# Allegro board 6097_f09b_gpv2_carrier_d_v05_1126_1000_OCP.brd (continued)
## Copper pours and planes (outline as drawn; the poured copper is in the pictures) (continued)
GND on IN1 (solid shape): 113.69,146.17 113.75,146.1 113.75,145.72 113.54,145.51 112.47,145.51 111,146.98 18.5,146.98 17.8,146.7 17.52,146 17.52,125.5 16.63,123.37 14.5,122.48 2,122.48 1.3,122.2 1.02,121.5 1.02,2 1.3,1.3 2,1.02 94.1,1.02 94.3,0.82 207.52,0.82 207.71,1.02 208,1.02 208.7,1.3 208.98,2 208.98,2.29 209,2.3 209,22.81 208.98,22.83 208.98,121.5 208.7,122.2 208,122.48 195.5,122.48 193.37,123.37 192.48,125.5 192.48,146 192.2,146.7 191.5,146.98 170.43,146.98 170.43,147.49 191.5,147.49 192.55,147.05 192.99,146 192.99,125.5 193.73,123.73 195.5,122.99 208,122.99 209.06,122.55 209.49,121.5 209.49,2 209.06,0.94 208,0.51 2,0.51 0.94,0.94 0.51,2 0.51,121.5 0.94,122.55 2,122.99 14.5,122.99 16.27,123.73 17.01,125.5 17.01,146 17.45,147.05 18.5,147.49 113.69,147.49
GND on IN1 (solid shape): outline of 6714 points within 161.24,2.17 207.32,50.16
GND on GND1 (solid shape): outline of 20227 points within 0.51,0.51 209.49,147.49
GND on VCC (solid shape): 114.63,40.62 116.4,40.62 116.56,40.45 116.56,37.53 114.78,35.75 106.34,35.75 106.01,36.08 106.01,39.36 107.98,41.32 113.92,41.32
GND on VCC (solid shape): 202.68,48.12 202.68,47.12 205.4,44.4 205.4,39.23 205.54,39.09 205.54,33.25 203.6,31.31 203.6,26.16 203.33,25.89 203.33,25.89 203.15,25.7 186.42,25.7 186.11,26.02 186.11,26.14 186.08,26.14 186.08,27.41 186.1,27.43 186.13,27.48 186.15,27.53 186.17,27.58 186.18,27.64 186.18,27.69 186.17,27.75 186.15,27.8 186.13,27.85 186.1,27.9 186.08,27.92 186.08,32.5 200.9,32.5 200.9,31.84 201.15,31.59 202.9,31.59 203.06,31.75 203.06,34.59 202.92,34.74 202.14,34.74 201.98,34.57 201.98,32.75 201.79,32.57 200.97,32.57 200.9,32.5 186.08,32.5 186.08,32.68 186.15,32.71 186.19,32.74 186.23,32.78 186.26,32.82 186.29,32.86 186.32,32.91 186.33,32.96 186.34,33.02 186.34,33.07 186.33,33.12 186.32,33.17 186.29,33.22 186.26,33.27 186.23,33.31 186.19,33.34 186.15,33.37 186.08,33.41 186.08,42.86 184.49,44.45 184.49,44.46 183.9,45.04 183.9,48 184.11,48.2 202.59,48.2
GND on VCC (solid shape): 206.02,105.7 206.29,105.7 206.62,105.38 206.65,105.21 206.51,105.12 206.34,105.12 206.12,104.89 206.12,104.57 206.34,104.34 206.66,104.34 206.85,104.53 206.93,104.54 206.98,104.47 206.98,104.33 207.19,104.12 207.19,104.08 207.41,103.86 207.45,103.86 208.29,103.01 208.29,77.56 207.53,76.8 207.53,73.58 208.25,72.86 208.25,58.25 206.4,56.41 206.4,50.29 208.32,48.37 208.32,39.03 207.63,38.35 207.63,30.71 207.49,30.57 207.08,30.57 206.9,30.74 206.9,31.42 207.36,31.87 207.36,38.54 208.02,39.2 208.02,48.24 206.06,50.2 206.06,56.68 207.93,58.55 207.93,59.43 208.01,59.67 207.93,59.91 207.93,72.65 207.19,73.38 207.19,77.02 207.99,77.81 207.99,101.82 205.55,104.26 205.55,105.77 205.96,105.77
GND on VCC1 (solid shape): 114.63,40.62 116.4,40.62 116.56,40.45 116.56,37.53 114.78,35.75 106.34,35.75 106.01,36.08 106.01,39.36 107.98,41.32 113.92,41.32
GND on VCC1 (solid shape): outline of 1285 points within 186.08,13.61 208.98,106.52
GND on GND2 (solid shape): outline of 23656 points within 0.51,0.51 209.49,147.49
GND on IN2 (solid shape): 121.76,37.61 121.87,37.51 121.87,36.61 121.69,36.43 118.25,36.43 118.04,36.64 118.04,40.33 118.14,40.43 121.76,40.43
GND on IN2 (solid shape): 33.5,39.43 33.42,39.35 33.42,39.19 33.01,38.79 33.01,36.92 31.9,36.92 31.53,36.55 30.24,36.55 30.03,36.76 30.03,39.68 30.43,40.08 32.86,40.08
GND on IN2 (solid shape): 197.16,32.56 197.27,32.52 197.41,32.37 197.41,30.61 197.32,30.47 197.15,30.5 196.58,31.07 196.58,32.24 196.63,32.36 196.75,32.4 196.91,32.42 197.05,32.51
GND on IN2 (solid shape): 111.19,39.36 111.19,36.26 110.43,35.5 106.48,35.5 106.28,35.7 106.28,36.75 108.28,36.75 108.28,36.7 108.3,36.64 108.32,36.59 108.34,36.54 108.38,36.5 108.42,36.46 108.46,36.43 108.51,36.4 108.56,36.38 108.62,36.37 108.68,36.37 108.73,36.38 108.78,36.39 108.84,36.41 108.88,36.44 108.93,36.48 108.96,36.52 108.99,36.57 109.02,36.62 109.03,36.67 109.04,36.73 109.04,36.78 109.03,36.84 109.02,36.89 108.99,36.94 108.96,36.99 108.93,37.03 108.88,37.06 108.84,37.09 108.78,37.12 108.73,37.13 108.68,37.14 108.62,37.13 108.56,37.12 108.51,37.11 108.46,37.08 108.42,37.05 108.38,37.01 108.34,36.96 108.32,36.92 108.3,36.86 108.28,36.81 108.28,36.75 106.28,36.75 106.28,39.58 106.7,40.01 110.53,40.01
GND on IN2 (solid shape): outline of 287 points within 15.58,19.54 22.54,27.85
GND on IN2 (solid shape): 113.69,146.03 114.23,145.49 115.07,145.49 115.56,145.99 115.56,147.49 118.44,147.49 118.44,146.16 118.44,146.03 118.98,145.48 119.79,145.48 120.31,146 120.31,147.49 120.31,147.49 167.26,147.49 167.26,146.98 128.23,146.98 128.23,146.98 127.25,146.98 125.55,145.28 111.89,145.28 111.32,145.86 111.32,146.74 111.08,146.98 18.5,146.98 17.8,146.7 17.52,146 17.52,125.5 16.63,123.37 14.5,122.48 2,122.48 1.3,122.2 1.02,121.5 1.02,2 1.3,1.3 2,1.02 208,1.02 208.7,1.3 208.98,2 208.98,121.5 208.7,122.2 208,122.48 195.5,122.48 193.37,123.37 192.48,125.5 192.48,146 192.2,146.7 191.5,146.98 170.62,146.98 170.62,147.49 191.5,147.49 192.55,147.05 192.99,146 192.99,125.5 193.73,123.73 195.5,122.99 208,122.99 209.06,122.55 209.49,121.5 209.49,2 209.06,0.94 208,0.51 2,0.51 0.94,0.94 0.51,2 0.51,121.5 0.94,122.55 2,122.99 14.5,122.99 16.27,123.73 17.01,125.5 17.01,146 17.45,147.05 18.5,147.49 113.69,147.49
GND on IN2 (solid shape): outline of 4770 points within 160.38,2.18 204.34,50.9
GND on GND3 (solid shape): outline of 24065 points within 0.51,0.51 209.49,147.49
P0V9_BOOTC on TOP (solid shape): 207.86,41.1 207.86,39.37 207.81,39.32 207.22,39.32 207.13,39.41 207.13,41.22 207.19,41.29 207.66,41.29
P0V9_VCC on TOP (solid shape): 208.73,38.35 208.73,37.55 207.79,37.55 207.71,37.47 207.55,37.47 207.54,37.46 207.46,37.45 207.41,37.52 207.41,37.75 208.05,38.39 208.69,38.39
P0V9_VDRV1 on TOP (solid shape): 201.23,37.15 201.23,36.41 201.2,36.38 200.28,36.38 200.18,36.47 198.93,36.47 198.76,36.3 198.76,34.75 198.15,34.75 198.15,35.43 198.09,35.48 197.31,35.48 197.28,35.51 197.28,37.06 197.49,37.27 201.11,37.27
P0V92 on TOP (solid shape): 204.41,50.11 204.41,44.82 203.59,43.99 201.01,43.99 201,43.98 200.92,43.98 200.54,43.61 200.54,42.25 200.42,42.13 200.35,42.2 200.34,42.22 199.94,42.53 199.59,42.16 199.59,42.09 188.31,42.09 188.14,42.25 188.14,44.11 187.7,44.55 184.88,44.55 184.75,44.68 184.75,48.69 184.95,48.88 187.32,48.88 187.46,48.74 187.46,47.26 187.48,47.24 187.48,47.23 187.81,46.9 196.35,46.9 196.43,46.98 196.7,46.98 196.8,47.09 196.8,49.83 197.33,50.36 204.16,50.36
P0V92 on BOTTOM (solid shape): 203.59,46.67 203.59,42.48 203.3,42.19 200.35,42.19 200.34,42.25 199.97,42.53 199.6,42.25 199.58,42.19 186.84,42.19 186.83,42.19 180.6,42.19 180.56,42.23 180.56,44.43 181.82,45.69 184.48,45.69 184.7,45.91 184.7,48.7 184.91,48.91 187.32,48.91 187.46,48.77 187.46,47.34 187.88,46.92 195.4,46.92 195.89,47.41 195.89,49.46 196.21,49.78 200.48,49.78
P0V92 on BOTTOM (solid shape): outline of 407 points within 190.91,93.13 204.56,101.19
P0V92 on BOTTOM (solid shape): outline of 3945 points within 176.33,70.62 191.16,88.48
P0V92 on IN1 (solid shape): outline of 3053 points within 176.33,72.8 190.83,88.24
P0V92 on VCC1 (solid shape): outline of 1190 points within 140.16,40.45 208.98,122.48
P0V92_SENSE+ on VCC (solid shape): outline of 230 points within 205.55,30.57 208.98,106.62
P1V8 on TOP (solid shape): 21.42,26.36 21.42,24.11 21.31,24.01 18.07,24.01 17.91,24.16 17.91,26.34 18.04,26.47 21.3,26.47
P1V8 on TOP (solid shape): 207.24,101.93 207.24,101.73 207.29,101.68 208.31,101.68 208.73,101.25 208.73,76.9 208.69,76.79 208.58,76.75 208.54,76.74 208.5,76.73 208.23,76.73 208.03,76.94 208.03,88.59 208.04,88.69 208.03,88.78 208.03,89.67 208.04,89.77 208.03,89.86 208.03,90.23 207.68,90.57 206.13,90.57 205.89,90.82 205.84,90.82 205.84,102.06 205.89,102.11 207.06,102.11
P1V8 on BOTTOM (solid shape): 2.44,40.23 2.44,38.53 2.13,38.23 1.3,38.23 1.27,38.25 1.27,40.28 2.39,40.28
P1V8 on BOTTOM (solid shape): 21.42,26.36 21.42,24.62 21.28,24.48 18.09,24.48 17.91,24.66 17.91,26.34 18.04,26.47 21.3,26.47
P1V8 on BOTTOM (solid shape): 205.06,81.36 205.06,78.11 204.83,77.88 203.41,77.88 203.41,78.81 203.76,79.17 203.76,79.25 203.86,79.35 203.86,81.25 204.02,81.41 205.01,81.41
P1V8 on BOTTOM (solid shape): 193.48,5.12 193.48,4.33 193.67,4.13 193.67,2.2 193.51,2.04 191.79,2.04 191.58,2.25 191.58,3.88 191.28,4.18 188.79,4.18 188.76,4.21 188.76,4.72 188.76,4.72 190.63,4.72 191.09,5.19 193.41,5.19
P1V8 on BOTTOM (solid shape): 3.22,32.43 3.31,32.3 3.43,32.22 3.45,32.21 3.82,31.84 3.82,30.97 3.7,30.85 2.46,30.85 2.37,30.94 2.37,32.43 2.39,32.45 3.21,32.45
P1V8 on BOTTOM (solid shape): 195.79,73.03 195.79,72.25 195.62,72.25 195.57,72.25 195.51,72.24 194.89,72.24 194.76,72.35 194.59,72.39 194.56,72.39 194.53,72.42 194.5,72.59 194.63,72.68 194.87,72.79 194.98,73.04 195.03,73.14 195.13,73.18 195.64,73.18
P1V8 on BOTTOM (solid shape): 192.81,75.21 192.81,74.84 192.79,74.81 192.57,74.49 192.68,74.12 192.68,73.85 192.83,73.69 193.28,73.69 193.33,73.65 193.53,73.58 193.73,73.6 193.78,73.61 194.24,73.15 194.24,73.11 194.24,73 194.27,72.89 194.3,72.84 194.21,72.75 194.03,72.92 194.03,72.98 193.97,72.98 193.8,73.15 191.45,73.15 191.2,73.4 191.27,73.47 191.34,73.58 191.37,73.72 191.37,74.29 191.78,74.7 191.79,74.7 191.9,74.82 191.96,74.97 191.96,74.99 192.25,75.29 192.73,75.29
P1V8 on BOTTOM (solid shape): outline of 908 points within 189.74,82.81 199.51,90.69
P1V8 on VCC (solid shape): outline of 14675 points within 1.02,1.02 208.98,146.98
P1V8 on IN2 (solid shape): outline of 2105 points within 188.73,69.79 199.18,86.29
P1V8 on IN2 (solid shape): outline of 3968 points within 61.89,2.2 149.25,46.23
P3V3 on TOP (solid shape): 192.04,140.81 192.04,139.77 191.45,139.18 187.59,139.18 187.54,139.23 187.54,140.38 188.55,140.38 188.59,140.38 188.63,140.39 189.87,140.39 190.4,140.91 191.93,140.91
P3V3 on BOTTOM (solid shape): 8.26,108.14 8.26,106.23 7.98,105.95 1.38,105.95 1.31,106.02 1.31,106.86 1.42,106.97 3.58,106.97 3.96,107.34 3.96,107.7 3.97,107.72 4.03,107.94 3.97,108.17 3.96,108.19 3.96,108.27 4.02,108.33 8.07,108.33
P3V3 on VCC (solid shape): outline of 630 points within 82.38,143.29 142.38,146.98
P3V3_BOOTC_2 on TOP (solid shape): 172.57,23.42 172.57,21.96 172.52,21.92 171.95,21.92 171.92,21.95 171.92,23.4 171.97,23.45 172.54,23.45
P3V3_BOOTC_3 on TOP (solid shape): 195.21,38.29 195.21,36.76 195.14,36.69 194.55,36.69 194.49,36.75 194.49,37.15 194.5,37.15 194.5,37.38 194.32,37.55 194.32,38.38 194.36,38.41 195.09,38.41
P3V3_DB1200 on BOTTOM (solid shape): outline of 578 points within 55.35,55.1 71.53,73.2
P3V3_DB1200_VDDA on BOTTOM (solid shape): 68.28,67.06 69.21,67.06 69.49,66.78 69.49,65.85 69.04,65.41 68.63,65.41 68.63,65.41 66.6,65.41 66.47,65.53 66.47,66.09 66.55,66.22 66.7,66.22 67.27,66.56 66.7,66.89 66.55,66.89 66.47,67.02 66.47,67.58 66.63,67.73 67.6,67.73
P3V3_DB1200_VDDR on BOTTOM (solid shape): 66.1,67.25 66.1,65.99 65.58,65.48 63.8,65.48 63.55,65.74 63.55,66.59 64.5,66.59 64.51,66.54 64.52,66.48 64.54,66.43 64.57,66.38 64.6,66.34 64.64,66.3 64.69,66.27 64.74,66.24 64.79,66.22 64.84,66.21 64.9,66.21 64.96,66.22 65.01,66.23 65.06,66.25 65.11,66.28 65.15,66.32 65.19,66.36 65.22,66.41 65.24,66.46 65.26,66.51 65.27,66.57 65.27,66.62 65.26,66.68 65.24,66.73 65.22,66.78 65.19,66.83 65.15,66.87 65.11,66.9 65.06,66.93 65.01,66.95 64.96,66.97 64.9,66.97 64.84,66.97 64.79,66.96 64.74,66.94 64.69,66.92 64.64,66.89 64.6,66.85 64.57,66.8 64.54,66.76 64.52,66.7 64.51,66.65 64.5,66.59 63.55,66.59 63.55,67.31 63.68,67.43 65.92,67.43
P3V3_M2A on TOP (solid shape): outline of 125 points within 23.36,111.32 31.14,114.83
P3V3_M2A_L on TOP (solid shape): outline of 406 points within 19.38,117.63 37.84,126.82
P3V3_M2B on TOP (solid shape): 55.2,114.65 55.2,113.75 55.14,113.63 55,113.61 54.5,113.24 55,112.88 55.14,112.86 55.2,112.74 55.2,112.19 55.2,112.18 55.2,112.14 54.99,111.94 54.24,111.94 53.38,111.07 49.24,111.07 49.23,111.06 48.93,111.06 48.63,111.36 48.63,111.89 48.63,111.96 48.04,112.56 48.04,114.35 48.07,114.38 50.23,114.38 50.34,114.33 50.38,114.21 50.38,114.17 50.38,113.54 50.77,113.14 51.16,113.54 51.16,114.17 51.16,114.25 51.13,114.32 51.11,114.37 51.32,114.58 51.32,114.77 51.39,114.83 55.01,114.83
P3V3_M2B_L on TOP (solid shape): outline of 97 points within 43.38,118.01 61.84,127.46
P3V3_M2C on TOP (solid shape): 80.16,113.61 80.16,112.44 80.06,112.34 79.95,112.29 79.84,112.34 79.31,112.33 79.31,111.8 79.35,111.69 79.3,111.58 79.12,111.4 79.08,111.4 77.94,110.26 73.7,110.26 73.53,110.44 73.53,111.17 72.56,112.14 72.56,113.07 72.82,113.32 75.14,113.32 75.26,113.27 75.29,113.15 75.29,113.1 75.29,112.52 75.61,112.2 76.17,112.2 76.17,112.76 76.08,112.85 76.08,113.1 76.07,113.16 76.05,113.24 76.05,113.32 76.15,113.32 76.26,113.43 78.55,113.43 78.93,113.81 79.96,113.81
P3V3_M2C_L on TOP (solid shape): outline of 100 points within 67.11,116.54 85.84,126.82
P3V3_M2D on TOP (solid shape): 105.91,113.84 105.91,113.43 105.85,113.31 105.71,113.29 105.21,112.93 105.71,112.57 105.85,112.55 105.91,112.42 105.91,111.26 105.63,110.98 102.7,110.98 102.57,110.85 98.67,110.85 98.4,111.12 98.4,114.04 98.45,114.1 100.54,114.1 100.65,114.05 100.69,113.93 100.69,113.9 100.69,113.29 101.08,112.89 101.48,113.29 101.48,113.9 101.47,113.95 101.46,114.01 101.46,114.1 101.56,114.1 101.67,114.21 105.54,114.21
P3V3_M2D_L on TOP (solid shape): outline of 96 points within 91.38,117.27 109.84,126.82
P3V3_M2E on TOP (solid shape): 128.78,114.14 128.78,112.5 128.57,112.29 127.42,112.29 126.27,111.14 123.02,111.14 122.89,111.27 122.89,111.93 122.38,112.44 122.38,114.25 124.49,114.25 124.6,114.2 124.64,114.08 124.64,114.03 124.64,113.4 124.95,113.08 125.51,113.08 125.51,113.64 125.43,113.73 125.43,114.03 125.42,114.09 125.4,114.17 125.4,114.25 125.51,114.25 125.58,114.32 128.6,114.32
P3V3_M2E_L on TOP (solid shape): outline of 88 points within 115.38,117.45 133.84,126.82
P3V3_M2F on TOP (solid shape): 157.2,114.03 157.2,112.48 157.12,112.4 154.24,112.4 153.01,111.16 149.94,111.16 149.49,111.61 149.46,111.61 149.13,111.94 148.93,111.94 148.84,111.96 148.77,111.97 148.53,111.97 148.37,112.13 148.37,113.45 148.58,113.66 152.07,113.66 152.19,113.61 152.22,113.49 152.22,113.39 152.25,113.3 152.28,113.22 152.34,113.16 152.35,113.15 152.35,113.08 152.41,113.08 152.54,112.95 153.24,112.95 153.66,113.37 153.66,114.66 156.57,114.66
P3V3_M2F_L on TOP (solid shape): outline of 248 points within 139.38,117.6 157.84,126.82
P3V3_M2G on BOTTOM (solid shape): 159.79,116.27 160.25,115.81 161.04,115.81 161.2,115.97 161.27,115.97 161.27,116.04 161.37,116.19 161.39,116.37 161.43,116.48 161.54,116.53 163.48,116.53 163.58,116.4 163.6,116.37 163.6,116.34 163.6,115.51 163.62,115.49 163.62,114.28 163.25,113.91 163.23,113.91 163.11,113.86 163,113.78 162.8,113.58 162.1,113.58 161.85,113.32 158.98,113.32 158.73,113.58 158.67,113.58 158.62,113.62 157.74,113.62 157.64,113.61 157.56,113.58 157.54,113.58 157.39,113.58 157.38,113.63 157.27,113.8 157.11,113.91 157.06,113.93 157.06,116.01 157.8,116.75 159.79,116.75
P3V3_M2G_L on BOTTOM (solid shape): outline of 1181 points within 148.58,119.56 168.06,134.07
P3V3_M2H on BOTTOM (solid shape): 132.23,113.47 132.26,113.32 132.34,113.19 132.6,112.94 133.28,112.94 133.46,113.12 133.53,113.12 133.53,113.18 133.58,113.24 133.61,113.3 133.65,113.41 133.65,113.52 133.69,113.64 133.8,113.69 135.92,113.69 135.92,111.67 135.54,111.29 135.5,111.3 135.3,111.28 135.12,111.17 135.04,111.09 133.1,111.09 133.08,111.1 131.92,111.1 130.57,112.46 128.95,112.46 128.89,112.52 128.89,113.57 129.07,113.74 132.23,113.74
P3V3_M2H_L on BOTTOM (solid shape): outline of 1501 points within 124.58,116.84 144.43,134.14
P3V3_M2I on BOTTOM (solid shape): outline of 89 points within 104.78,110.27 112.08,113.25
P3V3_M2I_L on BOTTOM (solid shape): outline of 1368 points within 100.02,116.37 120.66,134.27
P3V3_M2J on BOTTOM (solid shape): 82.72,112.94 82.75,112.79 82.84,112.66 83.14,112.36 83.75,112.36 83.97,112.59 84.04,112.59 84.04,112.65 84.05,112.66 84.15,112.82 84.16,113 84.2,113.11 84.32,113.16 86.43,113.16 86.44,113.15 86.44,110.99 85.85,110.41 79.59,110.41 79.42,110.58 79.42,112.22 79.47,112.32 79.57,112.37 79.9,112.58 79.87,112.97 79.86,113.12 80,113.21 82.72,113.21
P3V3_M2J_L on BOTTOM (solid shape): outline of 1598 points within 75.71,116.34 96.09,134.07
P3V3_M2K on BOTTOM (solid shape): 58.82,113.84 58.82,113.21 58.9,113.13 59.23,113.13 59.23,113.04 59.19,112.91 58.63,112.91 58.23,112.52 58.63,112.13 59.39,112.13 59.54,112.16 59.67,112.24 59.98,112.55 59.98,112.88 59.98,112.92 59.97,112.95 60,113.08 60.12,113.13 61.73,113.13 61.73,113.09 62.26,113.09 62.26,113.09 62.26,111.92 61.29,110.94 61.29,110.37 60.81,109.9 59.85,109.9 59.83,109.94 59.47,110.22 59.05,110.08 58.86,109.9 57.36,109.9 57.09,110.02 56.76,109.93 56.71,109.95 56.4,110.09 56.09,109.96 56.03,109.9 55.04,109.9 55.02,109.95 54.71,110.26 54.29,110.15 54.24,110.1 54.08,110.25 54.08,113.48 54.23,113.63 54.33,113.67 54.43,113.64 54.81,113.58 55.05,113.87 55.06,113.93 58.73,113.93
P3V3_M2K_L on BOTTOM (solid shape): outline of 1979 points within 51.9,116.94 72.54,134.16
P3V3_M2L on BOTTOM (solid shape): 35.9,115.25 36.28,114.87 36.99,114.87 37.12,114.88 37.24,114.94 37.29,114.98 37.41,115.15 37.44,115.35 37.47,115.47 37.59,115.52 39.53,115.52 39.53,115.46 39.61,115.29 39.64,115.26 39.64,114.63 38.61,113.6 38.61,112.85 36.87,112.85 36.75,112.97 32.76,112.97 31.74,113.99 31.52,114.11 31.28,114.09 31.26,114.09 31.18,114.09 31.18,114.28 31.27,114.37 31.27,114.38 31.27,114.91 31.39,115.04 32.39,115.04 32.39,115.04 35.2,115.04 35.72,115.56 35.9,115.56
P3V3_M2L_L on BOTTOM (solid shape): outline of 1753 points within 25.83,118.19 50.87,134.16
P3V3_STBY on TOP (solid shape): 11.59,33.9 11.59,33.03 11.38,32.82 9.99,32.82 9.96,32.84 9.96,33.98 10.12,34.13 11.36,34.13
P3V3_STBY on TOP (solid shape): 16.89,18.99 16.89,16.75 16.79,16.64 15.81,16.64 15.69,16.76 15.69,19 15.75,19.05 16.83,19.05
P3V3_STBY on TOP (solid shape): 32.72,35.26 32.72,34.62 31.29,33.2 30.2,33.2 30.05,33.35 30.05,34.64 30.2,34.79 30.2,34.98 30.58,35.36 32.61,35.36
P3V3_STBY on TOP (solid shape): 112.14,31.85 114.07,31.85 114.07,30.79 112.19,30.79 111.71,31.04 111.2,31.21 111.18,31.22 110.36,32.03 110.36,32.44 110.54,32.61 111.38,32.61
P3V3_STBY on TOP (solid shape): 98.72,116.98 98.72,116.35 98.79,116.28 101.43,116.28 101.5,116.21 101.5,114.39 101.46,114.35 98.35,114.35 97.89,113.9 97.89,110.14 96.95,109.19 95.22,109.19 94.9,109.52 94.9,115.39 95.02,115.52 96.63,115.52 97.08,115.97 97.08,116.23 97.13,116.28 97.83,116.28 97.9,116.35 97.9,116.73 98.15,116.98 98.72,116.98
P3V3_STBY on TOP (solid shape): 187.73,44.09 187.73,40.31 185.9,38.48 185.9,33.86 185.34,33.3 185.34,26.57 185.04,26.26 161.93,26.26 161.75,26.44 161.75,29.82 161.04,30.53 161.04,33.76 161.38,34.1 178.73,34.1 179.82,33.01 182.47,33.01 182.79,33.33 182.79,39.88 182.53,40.14 181.4,40.14 181.2,40.34 181.2,40.98 181.19,40.98 181.19,43.95 181.51,44.27 187.55,44.27
P3V3_STBY on TOP (solid shape): 115.89,142.98 116.06,142.82 117.55,142.82 117.82,142.54 117.82,142.53 118.07,142.29 120.42,142.29 122.59,144.46 124.84,144.46 124.89,144.4 124.89,143.94 125.09,143.74 125.28,143.74 125.29,143.73 126.8,143.73 126.83,143.7 126.83,142.17 124.7,140.05 115.03,140.05 114.72,140.36 114.72,142.36 115.52,143.17 115.52,144.51 115.89,144.51
P3V3_STBY on TOP (solid shape): 73.32,116.19 73.32,115.62 73.46,115.48 76.07,115.48 76.12,115.44 76.12,113.65 76.04,113.58 72.65,113.58 72.28,113.95 71.94,113.95 71.72,113.73 71.72,113.36 71.93,113.16 72.28,113.16 72.31,113.13 72.31,109.76 72.51,109.55 73.29,109.55 73.33,109.52 73.33,109.08 73.26,109.01 72.66,109.01 72.33,108.69 72.33,108.37 72.19,108.23 70.19,108.23 70.02,108.4 70.02,111.79 69.39,112.42 69.39,115.39 69.49,115.48 72.59,115.48 72.64,115.54 72.64,116.08 72.76,116.2 73.31,116.2
P3V3_STBY on TOP (solid shape): 122.67,117.12 122.67,116.49 122.74,116.41 125.42,116.41 125.5,116.34 125.5,114.6 125.41,114.51 122,114.51 121.94,114.44 121.94,112.37 122.47,111.83 122.47,110.99 121.92,110.44 120.52,110.44 120.12,110.04 119.94,110.04 119.13,109.23 118.83,109.23 118.68,109.38 118.68,116.28 118.81,116.41 119.96,116.41 120.06,116.31 120.06,115.94 120.17,115.82 120.96,115.82 120.98,115.85 120.98,116.36 121.03,116.41 121.88,116.41 121.97,116.5 121.97,117.04 122.05,117.12 122.67,117.12
P3V3_STBY on TOP (solid shape): 48.41,117.25 48.41,116.63 48.5,116.54 49.55,116.54 49.94,116.54 51.07,116.54 51.07,114.69 51.01,114.63 47.85,114.63 47.66,114.83 47.12,114.83 46.86,114.57 46.86,114.35 47.19,114.02 47.49,114.02 47.56,113.94 47.56,112.6 48.38,111.78 48.38,111.25 48.71,110.92 48.71,110.15 48.57,110.01 44.96,110.01 44.78,110.19 44.78,116.38 44.78,116.48 44.87,116.58 45.39,116.58 45.65,116.84 46.21,116.84 46.5,116.54 47.64,116.54 47.74,116.64 47.74,117.12 47.88,117.27 48.39,117.27
P3V3_STBY on TOP (solid shape): 21.26,117.35 21.26,117.15 21.49,116.92 22.99,116.92 23.06,116.98 23.06,117.61 23.1,117.65 23.69,117.65 23.7,117.64 23.7,117.01 23.72,116.99 26.28,116.99 26.29,116.98 26.29,115.18 26.23,115.11 23.32,115.11 22.87,114.66 22.87,113.02 23.66,112.22 23.66,111.48 23.66,111.33 23.66,111.01 22.97,110.31 21.54,110.31 21.52,110.36 21.16,110.62 20.8,110.37 20.37,110.37 20.15,110.59 20.15,110.95 20.08,111.03 19.73,111.03 19.68,111.07 19.68,115.29 20.29,115.89 20.29,117.65 20.35,117.72 20.89,117.72
P3V3_STBY on TOP (solid shape): 146.37,116.74 146.37,116.13 146.69,115.81 149.64,115.81 149.71,115.88 149.71,116.42 149.8,116.52 150.25,116.52 150.25,115.83 150.28,115.81 152.86,115.81 152.86,113.97 152.8,113.91 148.45,113.91 148.03,113.49 148.03,112.44 147.91,112.33 147.73,112.33 147.19,112.26 147.26,111.72 147.29,111.67 147.28,111.62 147.2,111.42 147.21,111.2 147.18,111.07 147.06,111.01 144.62,111.01 144.3,111.33 144.3,116.77 144.46,116.93 146.18,116.93
P3V3_STBY on TOP (solid shape): 187.61,132.55 190.6,132.55 191.51,131.64 191.51,129.27 191.1,128.87 185.96,128.87 185.78,129.05 185.78,130.58 185.86,130.67 186.08,130.67 186.46,131.05 186.46,131.17 188.85,131.17 188.85,130.49 188.85,130.45 188.86,130.38 188.88,130.3 188.9,130.23 188.93,130.16 188.97,130.1 189.01,130.04 189.07,129.99 189.12,129.94 189.18,129.9 189.25,129.86 189.32,129.84 189.39,129.82 189.46,129.8 189.54,129.8 189.61,129.8 189.69,129.82 189.76,129.84 189.83,129.86 189.89,129.9 189.95,129.94 190.01,129.99 190.06,130.04 190.11,130.1 190.14,130.16 190.18,130.23 190.2,130.3 190.22,130.38 190.22,130.45 190.22,130.49 190.22,131.17 190.22,131.21 190.22,131.28 190.2,131.36 190.18,131.43 190.14,131.49 190.11,131.56 190.06,131.62 190.01,131.67 189.95,131.72 189.89,131.76 189.83,131.8 189.76,131.82 189.69,131.84 189.61,131.85 189.54,131.86 189.46,131.85 189.39,131.84 189.32,131.82 189.25,131.8 189.18,131.76 189.12,131.72 189.07,131.67 189.01,131.62 188.97,131.56 188.93,131.49 188.9,131.43 188.88,131.36 188.86,131.28 188.85,131.21 188.85,131.17 186.46,131.17 186.46,132.84 186.5,132.88 187.28,132.88
P3V3_STBY on BOTTOM (solid shape): 9.56,32.94 9.56,32.94 10.1,32.39 10.1,31.03 9.91,30.84 9.03,30.84 8.82,31.05 8.82,32.95 8.94,33.07 9.42,33.07
P3V3_STBY on BOTTOM (solid shape): 4.06,105.28 4.06,103.89 3.93,103.75 2.94,103.75 2.86,103.67 2.86,103.1 2.73,102.97 1.37,102.97 1.33,103.01 1.33,105.32 1.39,105.38 3.96,105.38
P3V3_STBY on BOTTOM (solid shape): 185.9,39.4 185.9,38.11 185.51,38.11 185.51,35.45 185.9,35.45 185.9,33.86 185.26,33.21 185.26,32.06 185.04,31.85 185.04,31.34 184.75,31.05 184.75,28.53 184.41,28.18 184.41,26.25 161.38,26.25 161.04,26.59 161.04,33.78 161.36,34.1 179.54,34.1 179.83,33.81 179.83,33.27 180.13,32.97 182.28,32.97 182.78,33.47 182.78,39.37 183.01,39.6 185.7,39.6
P3V3_STBY on BOTTOM (solid shape): 86.54,116.03 86.54,115.3 86.61,115.23 88.51,115.23 88.7,115.42 90.58,115.42 90.65,115.34 90.65,110.65 90.65,110.64 90.65,109.07 90.48,108.89 87.61,108.89 87.3,109.2 87.3,112.44 86.79,112.95 86.79,113.3 86.67,113.42 83.56,113.42 83.56,115.33 85.98,115.33 86.13,115.48 86.13,116.04 86.15,116.06 86.51,116.06
P3V3_STBY on BOTTOM (solid shape): 112.16,116.02 112.16,115.47 112.27,115.35 112.84,115.35 112.85,115.37 114.96,115.37 114.97,115.35 114.97,108.42 114.83,108.28 112.22,108.28 112.06,108.44 112.06,109.51 112.06,109.51 112.06,109.96 112.53,110.43 112.53,113.43 112.51,113.45 111.71,113.45 111.65,113.5 109.19,113.5 109.19,115.35 111.69,115.35 111.78,115.44 111.78,116.07 111.8,116.1 112.08,116.1
P3V3_STBY on BOTTOM (solid shape): 37.12,53.85 37.12,53.32 37.05,53.25 36.66,53.25 36.54,53.13 36.54,52.28 36.73,52.08 37.56,52.08 37.61,52.02 37.68,51.96 37.71,51.94 37.71,51.47 37.61,51.37 36.29,51.37 36.22,51.37 36.14,51.37 35.33,51.37 35.31,51.37 35.16,51.4 35,51.37 34.98,51.37 34.89,51.37 34.58,51.67 34.58,53.8 34.68,53.9 37.07,53.9
P3V3_STBY on BOTTOM (solid shape): 62.26,115.95 62.26,115.33 62.34,115.26 65.33,115.26 65.53,115.05 65.53,108.22 64.91,108.22 64.67,108.46 64.67,109.78 64.45,110 63.43,110 63.41,109.98 62.83,109.98 62.79,110.02 62.79,113.32 62.76,113.35 61.98,113.35 61.98,113.39 59.36,113.39 59.3,113.39 59.14,113.56 59.14,115.26 61.89,115.26 61.94,115.31 61.95,115.32 61.95,115.97 61.97,116 62.22,116
P3V3_STBY on BOTTOM (solid shape): 68.1,70.92 68.1,68.35 67.92,68.17 67.22,68.17 67.08,68.26 67.1,68.43 67.16,68.83 66.82,69.05 66.72,69.1 66.67,69.21 66.67,70.89 66.89,71.11 67.9,71.11
P3V3_STBY on BOTTOM (solid shape): 136.21,116.55 136.21,115.85 136.69,115.51 137.16,115.85 138.74,115.85 138.76,115.87 140.24,115.87 140.37,115.74 140.37,110.29 140.03,109.96 137.25,109.96 136.88,110.33 136.74,110.33 136.33,110.73 136.33,113.82 136.2,113.95 133.04,113.95 133.04,115.85 135.59,115.85 135.62,115.89 135.62,116.55 135.63,116.56 136.21,116.56
P3V3_STBY on BOTTOM (solid shape): 40.17,118.25 40.17,118.02 40.26,117.92 41.41,117.92 41.63,118.14 42.24,118.14 42.42,117.96 42.42,111.1 42.4,111.08 39.52,111.08 39.3,110.86 39.3,110.48 39.24,110.42 38.85,110.42 38.82,110.45 38.82,111.08 38.51,111.4 38.51,112.05 38.58,112.12 38.9,112.12 39.03,111.98 39.9,111.98 40,112.08 40,115.26 39.83,115.42 39.81,115.48 39.79,115.53 39.79,115.73 39.74,115.77 36.8,115.77 36.79,115.79 36.79,117.69 37.17,117.69 39.3,117.69 39.35,117.75 39.35,118.39 39.35,118.39 40.02,118.39
P3V3_STBY on BOTTOM (solid shape): 166.94,119.44 166.94,117.68 167.41,117.21 167.41,112.82 167.21,112.62 166.07,112.62 165.55,112.84 165.43,112.96 164.35,112.96 163.87,113.44 163.87,115.6 163.86,115.61 163.86,116.34 163.84,116.45 163.78,116.56 163.77,116.58 163.77,116.72 163.8,116.72 163.73,116.79 160.7,116.79 160.61,116.89 160.61,118.59 160.72,118.7 162.37,118.7 162.37,118.71 163.34,118.71 163.36,118.73 163.36,119.42 163.41,119.46 163.9,119.46 163.95,119.41 163.95,118.77 164.02,118.71 165.18,118.71 165.55,118.46 165.91,118.71 166.22,118.71 166.41,118.89 166.41,119.45 166.47,119.51 166.88,119.51
P3V3_STBY on BOTTOM (solid shape): 9.6,41.59 9.6,40.46 9.51,40.32 9.35,40.34 8.61,39.98 9.35,39.62 9.51,39.64 9.6,39.5 9.6,38.36 8.86,37.62 7.37,37.62 7.24,37.74 7.24,37.77 6.99,38.02 6.96,38.02 6.78,38.2 6.76,38.2 6.58,38.38 6.58,39.37 6.66,39.45 7.04,39.45 7.08,39.49 7.15,39.52 7.22,39.55 7.35,39.55 7.35,39.66 7.39,39.74 7.42,39.82 7.43,39.84 7.49,39.9 7.47,39.93 7.47,40.16 7.59,40.28 7.65,40.28 8.36,41 8.36,41.4 8.69,41.73 9.45,41.73
P3V3_STBY on BOTTOM (solid shape): 44.77,44.49 44.81,44.36 44.75,44.25 44.73,43.64 45.31,43.84 45.33,43.89 45.66,43.89 45.71,43.89 45.75,43.88 47.17,43.88 47.78,43.27 47.78,42.94 47.9,42.82 48.59,42.82 49.07,43.3 49.07,43.89 49.26,44.07 49.86,44.07 50.48,43.45 50.51,43.37 50.55,43.32 50.55,40.95 50.54,40.89 50.53,40.84 50.53,40.7 50.37,40.54 49.48,40.54 49.3,40.72 49.3,40.97 49.84,41.5 49.84,42.29 49.53,42.6 49.15,42.6 48.82,42.27 45.5,42.27 45.5,42.33 45.31,42.52 45.3,42.54 45.17,42.74 44.94,42.82 44.84,42.86 44.79,42.95 44.39,43.29 44.04,42.89 44.03,42.84 43.97,42.81 43.95,42.81 43.89,42.83 43.87,42.9 43.79,43.17 43.43,43.37 43.4,43.49 43.4,43.53 43.4,43.57 43.42,43.62 43.47,43.65 43.72,43.8 43.79,44.08 43.8,44.14 43.85,44.17 44.03,44.26 44.13,44.43 44.19,44.52 44.29,44.54 44.42,44.56 44.54,44.62 44.6,44.66
P3V3_STBY on BOTTOM (solid shape): 36.53,48.39 36.53,48.11 36.88,47.75 37.64,47.75 37.67,47.73 38.16,47.73 38.28,47.62 38.44,47.58 38.53,47.54 38.58,47.45 38.95,47.12 39.32,47.44 39.35,47.49 39.41,47.51 39.48,47.51 39.56,47.52 39.8,47.52 39.89,47.61 39.96,47.54 39.96,47.51 40.21,47.24 40.56,47.36 40.64,47.42 40.75,47.41 40.95,47.38 41.14,47.47 41.25,47.51 41.35,47.47 41.43,47.4 41.43,46.2 41.6,46.03 41.61,46.02 41.81,45.82 42.62,45.82 42.62,45.8 43.1,45.31 43.31,45.31 43.41,45.21 43.41,44.63 43.4,44.55 43.4,44.47 43.39,44.42 43.35,44.38 43.13,44.24 43.05,43.99 43.04,43.93 42.99,43.91 42.8,43.83 42.68,43.66 42.61,43.58 42.51,43.57 42.31,43.54 42.15,43.41 41.7,43.41 41.66,43.46 41.66,45.36 41.43,45.59 41.43,45.75 41.07,46.1 39.45,46.1 39.33,46.22 39.34,46.26 39.19,46.7 38.73,46.65 38.28,46.65 38.18,46.74 37.5,46.74 37.33,46.91 35.89,46.91 35.89,46.91 35.89,48.44 35.94,48.49 36.42,48.49
P3V3_STBY on VCC (solid shape): outline of 5037 points within 17.78,3.64 185.57,120.12
P3V3_STBY on VCC1 (solid shape): outline of 17072 points within 1.02,1.02 194.71,146.98
P3V3_STBY_CPLD_JTAG on TOP (solid shape): 7.14,36.62 7.85,36.62 7.87,36.6 7.87,34.57 8.61,33.83 8.61,32.92 5.79,32.92 4.03,34.68 4.03,35.96 3.81,36.18 3.81,36.65 3.94,36.78 6.99,36.78
P3V3_STBY_VCC on TOP (solid shape): 173.82,20.13 173.27,19.59 172.3,19.59 172.3,19.59 172.3,20.04 172.32,20.06 172.94,20.06 173.34,20.46 173.34,21.09 173.82,21.09
P3V3_STBY_VDRV1 on TOP (solid shape): 174.63,21.08 174.63,20.6 174.95,20.27 177.28,20.27 177.31,20.24 177.31,19.95 177.27,19.91 175.8,19.91 175.69,19.8 174.63,19.8 174.54,19.71 174.54,17.88 174.46,17.81 173.93,17.81 173.87,17.87 173.87,19.76 174.14,20.03 174.14,21.08 174.17,21.11 174.59,21.11
P3V3_STBY_VDRV2 on TOP (solid shape): 163.5,20.24 166.09,20.24 166.12,20.22 166.12,19.94 166.09,19.91 164.73,19.91 164.41,19.59 163.68,19.59 163.59,19.5 163.59,18.67 163.46,18.54 162.92,18.54 162.92,20.27 162.94,20.29 163.45,20.29
P3V3_STBY_VDRV3 on TOP (solid shape): 187.83,34.67 189.66,34.67 189.66,34.42 189.61,34.37 187.96,34.37 187.58,33.98 187.58,32.49 187.44,32.35 187.06,32.35 187.05,32.36 187.05,34.11 186.94,34.21 186.41,34.21 186.33,34.29 186.33,34.85 186.39,34.9 187.6,34.9
P12V_CONN on TOP (solid shape): 96.88,30.84 96.88,25.28 96.66,25.06 90.86,25.06 90.3,25.62 90.3,30.87 90.59,31.17 96.55,31.17
P12V_CONN on TOP (solid shape): outline of 136 points within 72.15,1.27 168.3,10.92
P12V_CONN on BOTTOM (solid shape): 164.5,9.78 166.46,9.78 166.48,9.76 166.48,7.6 166.85,7.23 168.03,7.23 168.58,6.68 168.58,6.64 168.58,6.49 168.6,6.33 168.61,6.33 168.61,2.62 168.3,2.32 162.99,2.32 162.6,2.72 162.6,9.72 162.67,9.79 164.49,9.79
P12V_CONN on BOTTOM (solid shape): outline of 379 points within 72.1,1.47 96.67,31.37
P12V_CONN on VCC (solid shape): outline of 1448 points within 73,3.3 168.07,30.72
P12V_CONN on VCC1 (solid shape): outline of 2494 points within 73,1.02 168.07,30.71
P12V_CONN on IN2 (solid shape): outline of 1040 points within 72.24,1.62 168.12,31.23
P12V_STBY on TOP (solid shape): 103.98,31.12 103.98,24.98 103.57,24.56 99.12,24.56 98.58,25.11 98.58,30.45 99.75,31.62 103.48,31.62
P12V_STBY on TOP (solid shape): 206.37,9.15 206.37,3.05 206.19,2.87 202.69,2.87 202.4,3.16 202.4,9.21 202.58,9.38 206.14,9.38
P12V_STBY on BOTTOM (solid shape): 206.69,8.77 206.69,2.89 206.4,2.6 200.61,2.6 200.29,2.92 200.29,8.79 200.6,9.1 206.36,9.1
P12V_STBY on BOTTOM (solid shape): 103.98,31.12 103.98,24.98 103.57,24.56 99.12,24.56 98.58,25.11 98.58,28.33 98.72,28.33 99.11,28.72 98.72,29.12 98.58,29.12 98.58,30.45 99.75,31.62 103.48,31.62
P12V_STBY on IN1 (solid shape): 103.98,31.12 103.98,24.98 103.57,24.56 99.12,24.56 98.58,25.11 98.58,30.45 99.75,31.62 103.48,31.62
P12V_STBY on VCC (solid shape): outline of 2909 points within 95.15,2.62 206.87,31.47
P12V_STBY on VCC1 (solid shape): outline of 3257 points within 95.15,1.02 208.98,31.47
P12V_STBY on IN2 (solid shape): 103.97,31.12 103.97,24.97 103.57,24.56 99.12,24.56 98.58,25.11 98.58,30.45 99.75,31.62 103.47,31.62
VCCIO_PLD_1_5 on BOTTOM (solid shape): 7.32,43.13 7.32,41.15 7.14,40.97 6.79,40.97 6.77,40.98 6.6,41.01 6.44,40.98 6.42,40.97 6.13,40.97 6.12,40.98 5.94,41.02 5.76,40.98 5.73,40.96 5.62,40.89 5.54,40.78 5.54,40.77 5.41,40.64 5.41,39.37 5.64,39.14 6.05,39.14 6.12,39.07 6.12,38.15 6.5,37.77 6.88,37.77 6.99,37.67 6.99,36.83 6.83,36.68 2.31,36.68 2.16,36.83 2.16,37.74 2.69,38.28 2.69,40.16 2.77,40.23 3.66,40.23 3.84,40.41 3.84,43.18 3.91,43.26 7.19,43.26
VCCIO_PLD_1_5 on VCC (solid shape): 21.26,57.26 21.26,42 20.79,41.53 16.39,41.53 16.12,41.65 15.85,41.53 9.66,41.53 9.35,41.68 9.05,41.53 5.95,41.53 5.26,42.22 5.26,54.3 8.44,57.48 21.04,57.48
VCCIO_PMOS_1_S on BOTTOM (solid shape): 2.21,35.62 2.21,34.7 2.04,34.53 2.04,30.66 2.32,30.38 2.32,29.55 2.16,29.39 1.31,29.39 1.27,29.43 1.27,35.6 1.34,35.67 2.16,35.67
VCCIO_PMOS_2_S on BOTTOM (solid shape): 5.82,35.6 5.82,34.67 5.58,34.43 5.58,33.55 5.79,33.34 7.11,33.34 7.35,33.09 7.49,33.09 7.51,33.08 8.26,33.08 8.51,32.83 8.51,31 8.84,30.67 8.84,29.52 8.8,29.49 8.73,29.49 8.66,29.42 7.94,29.42 7.88,29.49 7.88,30.28 7.5,30.66 7.5,32.04 7.26,32.29 6.74,32.29 6.55,32.47 6.55,32.5 6.53,32.5 6.43,32.6 5.59,32.6 4.9,33.29 4.9,35.65 4.96,35.71 5.72,35.71
VDD_P1V8_ZL30281 on TOP (solid shape): 117.79,38.78 117.79,38.02 116.33,38.02 115.93,37.62 114.35,37.62 114.3,37.67 114.3,38.1 114.38,38.18 115.62,38.18 115.93,38.48 116.21,38.48 116.54,38.81 117.75,38.81
VDD_P3V3_ZL30281 on TOP (solid shape): 123.95,36.11 123.95,33.64 122.85,33.64 122.67,33.82 122.67,35.9 122.09,36.47 122.13,36.51 122.13,36.83 123.23,36.83
VDD_P3V3_ZL30281 on TOP (solid shape): 120.81,35.19 120.81,34.77 120.34,34.3 120.34,33.02 120.22,32.9 118.35,32.9 118.19,33.07 118.19,34.21 118.32,34.35 118.9,34.35 119.21,34.66 119.21,35.15 119.32,35.25 120.75,35.25
VDD_P3V3_ZL30281 on TOP (solid shape): 117.79,36.53 117.86,36.46 117.86,36.26 117.76,36.17 117.04,36.17 116.87,36 116.87,35.54 115.91,34.58 115.91,30.77 115.77,30.63 114.48,30.63 114.36,30.75 114.36,31.38 114.36,31.38 114.36,32.12 114.36,32.12 114.36,35.67 114.55,35.87 115.04,35.87 115.23,36.05 115.26,36.06 115.52,36.17 115.65,36.42 115.66,36.45 115.89,36.67 115.94,36.71 116.05,36.71 116.05,36.82 117.79,36.82
VDD_P3V3_ZL30281 on BOTTOM (solid shape): outline of 388 points within 114.49,32.4 124.54,42.28
VDDC_OUTPUT on BOTTOM (solid shape): outline of 112 points within 37.13,42.95 39.22,45
VDDC_OUTPUT on BOTTOM (solid shape): outline of 128 points within 41.78,41.15 43.86,43.16
VDDC_OUTPUT on IN2 (solid shape): outline of 548 points within 37.12,39.83 43.84,44.93
VDDO_1V8 on BOTTOM (solid shape): outline of 1689 points within 190.3,75.77 203.51,83.57
VDDO_1V8 on IN1 (solid shape): outline of 559 points within 188.81,79.85 192.71,87.27
AVD_PCIE on TOP (solid shape): 184.01,48.39 184.01,44.76 183.89,44.64 181.15,44.64 180.46,43.95 175.77,43.95 175.62,44.1 175.62,45.63 182.42,48.44 183.48,48.44 183.49,48.45 183.95,48.45
AVD_PCIE on BOTTOM (solid shape): 184.07,48.41 184.07,46.02 184,45.96 181.64,45.96 180.35,44.67 179.75,44.67 179.74,44.67 176.84,44.67 176.63,44.88 176.63,46.8 178.26,48.43 178.61,48.58 183.9,48.58
AVD_PCIE on BOTTOM (solid shape): outline of 11424 points within 146.17,59.1 198.58,96.93
AVD_PCIE on IN1 (solid shape): outline of 11216 points within 165.79,66.29 195.7,98.94
AVD_PCIE on GND1 (solid shape): 191.84,97.48 191.84,96.45 192.22,96.07 192.22,96.04 192.33,95.76 192.61,95.65 192.64,95.65 193.95,94.33 197.69,94.33 197.83,94.19 197.83,91.99 197.65,91.81 173.29,91.81 172.84,91.36 172.84,70.72 173.27,70.29 184.91,70.29 185.48,70.86 185.48,71.87 185.9,72.29 190.9,72.29 190.9,69.8 192.02,68.68 192.4,68.68 192.86,68.21 192.86,67.83 192.79,67.76 183.77,67.76 182.73,66.72 176.14,66.72 175.95,66.9 175.96,66.94 175.86,67.29 175.51,67.39 175.47,67.39 175.08,67.77 171.14,67.77 170.84,67.47 170.84,66.85 170.76,66.78 166.48,66.78 166.34,66.92 166.34,95.46 167.3,96.42 167.3,97.97 167.61,98.28 191.04,98.28
AVD_PCIE on VCC (solid shape): outline of 681 points within 156.15,44.18 202.83,111.97
AVD_PCIE on IN2 (solid shape): outline of 1106 points within 191.43,64.1 197.63,69.13
AVD_PCIE on IN2 (solid shape): outline of 11323 points within 170.28,66.6 189.81,93.32
AVD_PCIE_Q on BOTTOM (solid shape): 176.46,90.6 176.46,90.56 176.45,90.46 176.47,90.36 176.48,90.34 176.48,89.71 176.47,89.7 176.45,89.56 176.47,89.43 176.48,89.42 176.48,89.18 176.81,88.85 176.81,88.83 176.69,88.71 176.09,88.71 176.09,90.7 176.37,90.7
AVD_PCIE_Q on BOTTOM (solid shape): 189.96,82.01 189.96,81.45 189.92,81.34 189.81,81.29 189.74,81.29 189.66,81.26 189.03,81.26 189.01,81.27 188.9,81.29 188.79,81.28 188.77,81.31 188.76,81.34 188.74,81.4 188.74,81.45 188.75,81.53 188.75,81.61 188.74,81.65 188.96,81.86 188.99,81.86 189.18,81.87 189.34,81.97 189.49,82.12 189.54,82.15 189.59,82.16 189.66,82.17 189.72,82.19 189.77,82.2
AVD_PCIE_Q on BOTTOM (solid shape): 184.92,72.35 184.92,71.55 184.92,71.49 184.94,71.42 184.94,71.38 184.89,71.31 184.42,71.35 184.22,71.02 184.19,70.97 184.14,70.94 183.82,70.94 183.73,71.04 183.73,71.1 183.73,71.11 183.76,71.25 183.73,71.38 183.73,71.39 183.73,72.04 183.73,72.05 183.76,72.19 183.73,72.32 183.73,72.33 183.73,72.42 183.78,72.47 184.79,72.47
AVD_PCIE_Q on BOTTOM (solid shape): 184.3,89.78 184.59,89.65 184.87,89.78 185.04,89.78 185.24,89.58 185.24,89.16 185.24,89.15 185.22,89.02 185.24,88.89 185.24,88.88 185.24,88.6 184.99,88.35 184.93,88.39 184.58,88.53 184.23,88.38 184.16,88.31 184.02,88.31 183.93,88.37 183.78,88.41 183.74,88.43 183.75,88.6 183.7,88.76 183.69,88.78 183.69,89.16 183.76,89.23 183.76,89.36 183.76,89.37 183.78,89.49 183.76,89.6 183.76,89.61 183.76,89.73 183.81,89.78
AVD_PCIE_Q on BOTTOM (solid shape): 176.87,72.22 176.87,71.96 176.79,71.89 176.77,71.89 176.69,71.86 176.62,71.82 176.6,71.81 176.58,71.81 176.58,71.78 176.56,71.76 176.45,71.54 176.49,71.31 176.5,71.29 176.5,70.76 176.49,70.75 176.45,70.61 176.46,70.47 176.45,70.42 176.42,70.39 176.37,70.36 175.81,70.36 175.8,70.37 175.73,70.4 175.66,70.42 175.6,70.43 175.6,70.64 175.66,70.65 175.96,71.02 175.66,71.39 175.6,71.4 175.6,71.64 175.66,71.65 175.91,71.82 175.95,72.12 175.97,72.25 176.09,72.31 176.77,72.31
AVD_PCIE_Q on BOTTOM (solid shape): outline of 228 points within 198.91,86.02 204.5,92.92
AVD_PCIE_Q on IN1 (solid shape): outline of 8171 points within 171.63,68.96 203.31,93.75
AVD_PCIE_Q on GND1 (solid shape): 202.54,92.71 202.54,87.39 201.93,86.78 198.08,86.78 197.68,86.38 197.64,86.39 197.32,86.28 197.22,85.96 197.23,85.92 197.12,85.81 194.37,85.81 193.96,85.4 193.96,81.94 193.44,81.41 191.61,81.41 190.9,80.7 190.9,73.05 190.65,72.8 185.69,72.8 184.98,72.08 184.98,71.07 184.7,70.79 173.48,70.79 173.35,70.93 173.35,91.15 173.5,91.3 197.86,91.3 198.34,91.77 198.34,93.29 201.96,93.29
AVD_PCIE_TX on TOP (solid shape): 176.1,43.18 176.1,40.92 175.95,40.76 172.72,40.76 172.36,41.12 172.36,42.74 172.96,43.33 175.95,43.33
AVD_PCIE_TX on BOTTOM (solid shape): 179.7,44.36 179.7,41.98 179.66,41.94 177.49,41.94 176.75,41.2 172.61,41.2 172.36,41.45 172.36,43.54 173.24,44.42 179.64,44.42
AVD_PCIE_TX on BOTTOM (solid shape): outline of 3347 points within 163.45,74.35 175.74,86.69
AVD_PCIE_TX on VCC (solid shape): 175.86,87.26 175.86,74.99 175.67,74.8 164.62,74.8 163.67,73.85 163.67,63.77 165.05,62.38 165.05,55.2 175.79,44.46 175.79,43.39 175.79,41.61 175.64,41.46 170.59,41.46 156.15,55.91 156.15,85.79 156.51,86.16 171.05,86.16 172.18,87.29 175.83,87.29
AVD_PCIE_TX on IN2 (solid shape): outline of 936 points within 170.31,74.73 175.31,86.28
OSC1_VDD on TOP (solid shape): 31.62,38.15 31.62,35.92 31.37,35.66 29.39,35.66 29.24,35.81 29.24,37.34 29.29,37.39 30.15,37.39 30.45,37.69 30.45,38.07 30.58,38.2 31.57,38.2
OSC1_VDD_R on TOP (solid shape): 29.68,41.01 29.68,39.72 29.77,39.63 29.77,38.4 29.95,38.23 29.95,37.74 28.98,37.74 28.63,37.39 27.23,37.39 27.2,37.41 27.2,39.37 27.2,41.05 27.36,41.2 29.49,41.2
SW_P0V9_1 on TOP (solid shape): 205.86,43.27 205.86,40.78 205.95,40.69 206.61,40.69 206.86,40.44 206.86,39.08 206.64,38.85 204.63,38.85 203.87,38.09 203.87,35.01 203.84,34.98 202.4,34.98 202.37,35.01 202.37,38.97 202.24,39.1 201.05,39.1 200.95,39.21 200.95,43.57 201.11,43.74 205.39,43.74
SW_P0V9_BT_1 on TOP (solid shape): 207.79,38.97 207.79,38.57 207.16,37.94 207.16,37.77 206.93,37.54 206.93,37.02 206.56,36.64 206.21,36.64 205.93,36.36 205.47,36.36 205.43,36.36 205.39,36.35 205.26,36.35 205.24,36.36 205.23,36.35 205.04,36.35 205.01,36.37 205.01,36.87 205.17,37.03 206.22,37.03 206.51,37.32 206.51,38.36 207.16,39.02 207.74,39.02
SW_P1V8 on TOP (solid shape): 20.73,22.76 20.73,21.95 20.68,21.9 20.13,21.9 19.82,21.59 19.82,20.76 19.8,20.74 19.58,20.74 19.55,20.76 19.55,21.61 19.23,21.93 18.77,21.93 18.64,22.07 18.64,22.85 18.67,22.88 20.6,22.88
SW_P1V8_FLT on TOP (solid shape): 19.3,21.5 19.3,20.7 19.27,20.67 18.73,20.67 18.41,20.35 18.41,18.19 18.25,18.04 17.5,18.04 17.35,18.19 17.35,21.57 17.43,21.64 19.16,21.64
SW_P3V3_STBY_1 on TOP (solid shape): 183.41,25.65 183.41,24.16 183.35,24.1 182.72,24.1 182.51,23.89 182.51,22.69 182.43,22.62 181.77,22.62 181.45,22.3 181.45,22.11 181.38,22.04 180.63,22.04 179.94,21.36 179.94,18.58 179.91,18.55 178.42,18.55 178.41,18.56 178.41,25.6 178.57,25.76 183.3,25.76
SW_P3V3_STBY_2 on TOP (solid shape): 172.58,25.58 172.58,23.84 172.52,23.78 171.82,23.78 171.64,23.6 171.64,22.14 171.55,22.05 169.37,22.05 168.7,21.38 168.7,18.57 167.21,18.57 167.21,25.63 167.34,25.76 172.4,25.76
SW_P3V3_STBY_3 on TOP (solid shape): 194.01,39.7 194.01,37.82 193.96,37.77 193.32,37.77 193.08,37.54 193.08,36.3 193.03,36.25 192.77,36.25 192.28,35.76 192.28,33.05 192.23,32.99 190.78,32.99 190.76,33.02 190.76,39.65 190.96,39.85 193.85,39.85
SW_P3V3_STBY_BT_1 on TOP (solid shape): 183.43,21.81 183.43,21.14 183.3,21.02 183.09,21.02 181.97,19.89 181.07,19.89 181.02,19.93 181.02,20.22 181.08,20.28 181.7,20.28 182.76,21.34 182.76,21.79 182.84,21.87 183.37,21.87
SW_P3V3_STBY_BT_2 on TOP (solid shape): 172.57,21.52 172.57,20.78 171.71,19.91 169.85,19.91 169.85,20.22 171.28,20.22 171.98,20.92 171.98,21.55 172,21.57 172.52,21.57
SW_P3V3_STBY_BT_3 on TOP (solid shape): 195.18,36.37 195.18,35.18 194.36,34.37 193.42,34.37 193.37,34.42 193.37,34.65 193.42,34.7 193.98,34.7 194.49,35.2 194.49,36.38 194.54,36.43 195.11,36.43
SW_P12V_FLT on TOP (solid shape): outline of 488 points within 168.61,5.15 206.81,38.52
TDR_GND on GND (solid shape): outline of 102 points within 0.51,-172.06 421.49,-127.99
TDR_GND on GND1 (solid shape): outline of 102 points within 0.51,-172.06 421.49,-127.99
TDR_GND on VCC (solid shape): outline of 102 points within 0.51,-172.06 421.49,-127.99
TDR_GND on VCC1 (solid shape): outline of 102 points within 0.51,-172.06 421.49,-127.99
TDR_GND on GND2 (solid shape): outline of 102 points within 0.51,-172.06 421.49,-127.99
TDR_GND on GND3 (solid shape): outline of 102 points within 0.51,-172.06 421.49,-127.99
TGND on GND (solid shape): outline of 6067 points within 0.51,125.99 421.49,163.2
TGND on GND1 (solid shape): outline of 5424 points within 0.51,125.99 421.49,163.2
TGND on VCC (solid shape): outline of 5424 points within 0.51,125.99 421.49,163.2
TGND on VCC1 (solid shape): outline of 5424 points within 0.51,125.99 421.49,163.2
TGND on GND2 (solid shape): outline of 5424 points within 0.51,125.99 421.49,163.2
TGND on GND3 (solid shape): outline of 6068 points within 0.51,125.99 421.49,163.2

Small or netless copper shapes (teardrops, artwork), in the pictures only: 6 on TOP, 1 on GND, 2 on IN1, 3 on IN2

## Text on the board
Ref Des/Silkscreen Bottom: J6A | J6B | J34A | J34B | J8A | J8B | G | B | CPLD | A | PCIE_SW_FLASH
User.Comments: Baseboard Rev.2A | TEL:(03)327-2345 FAX:(03)397-3614 | PROJECT: | P/N: | DATE: | LIB: | REV: | Tool: | NO.188,WEN HWA 2ND RD. | KUEI SHAN HSIANG,TAO YUAN | SHIEN,TAIWAN R.O.C. | Layer | Larry | DAF09BPCAD0 | 2019/11/26 | F09B_GPV2_Carrier_BD | 16.6 | D | IST GERBER(TVX10166A) | Quanta
Ref Des/Silkscreen Top: Aa | H | W | J4B | J4A | J36B | J36A | J38B | J38A | E | D | R | C | A | Q | B | O | J | BIC | M | P | S | U | T | V | X | Y | a | I | N | Z | P/N:DAF09BPCAD0 | Rev:D
User.13: 16.5 | 19.43 | 36.83 | 40.68 | 40.03 | 43.43 | 60.83 | {\Fgdt;n}\Ftxt;2.7 | 64.03 | 67.43 | 84.83 | 88.68 | 91.43 | 88.03 | 104.33 | 108.83 | 112.03 | 115.43 | 115.7 | 132.83 | 136.68 | 139.43 | 136.03 | 156.83 | {\Fgdt;n}\Ftxt;3.2x2 | 160.03 | 167.34 | 167.7 | 170.84 | {\Fgdt;n}\Ftxt;2.15x12 | {\Fgdt;n}\Ftxt;3.2x24 | 193.5 | 143.88 | 143.15 | 135.7 | 146.7 | 104.77 | 55.77 | 1.57 | 20.8 | 147.5 | 143.5 | 123.5 | 116 | 28.05 | 26.45 | 19 | 21.25 | 19.2 | 14 | 4 | 0 | {\Fgdt;n}\Ftxt;4x4 | 7.5 | 148 | 16.48 | 27.08 | 28.68 | 30 | 30.28 | 38.43 | 133.22 | 51.08 | 52.68 | 54.28 | 62.43 | 75.08 | 76.68 | 78.28 | 82.2 | 86.43 | 99.08 | 100.68 | 101.2 | 102.28 | 110.43 | 123.08 | 124.68 | 126.28 | 134.43 | 147.08 | 148.68 | 150.28 | 169.4 | 176.98 | {\Fgdt;n}\Ftxt;3.1x2 | 198.84 | 202.5 | 210
User.15: {\Fgdt;n}\Ftxt;3.3x5\PHOLE_C7D3-3B5_NPB | {\Fgdt;n}\Ftxt;4x5\PGND_C10D4 | 16.5 | 18.68 | 19.43 | 28.42 | 36.83 | 40.68 | 40.03 | 43.43 | 60.83 | 62.68 | 66.68 | 64.03 | 67.43 | 72.42 | 76.42 | 84.83 | 88.68 | 91.43 | 88.03 | 104.33 | 108.83 | 110.68 | 114.68 | 112.03 | 115.43 | 115.7 | 120.42 | 124.42 | 132.83 | 136.68 | 139.43 | 136.03 | 156.83 | 158.68 | 160.03 | 167.34 | 167.7 | 168.42 | {\Fgdt;n}\Ftxt;2.15x12 | {\Fgdt;n}\Ftxt;3.2x24 | 193.5 | 143.88 | 143.15 | 146.7 | 104.77 | 55.77 | 123.5 | 116 | 1.57 | 147.5 | 4 | 0 | 128.25 | 135.5 | 7.5 | 148 | 16.48 | 27.08 | 28.68 | 30 | 30.28 | 38.43 | 143.5 | 51.08 | 52.68 | 54.28 | 62.43 | 75.08 | 76.68 | 78.28 | 82.2 | 86.43 | 90.5 | 99.08 | 100.68 | 101.2 | 102.28 | 110.43 | 123.08 | 124.68 | 126.28 | 134.43 | 147.08 | 148.68 | 150.28 | 169.4 | 176.98 | {\Fgdt;n}\Ftxt;3.1x2 | 198.84 | 202.5 | 210
User.16: 31.54 | 210 | 130.3 | 43.1 | 0 | 135.7 | 148 | 4.98
User.17: {\Fgdt;n}\Ftxt;4x5\PGND_C10D4B10 | {\Fgdt;n}\Ftxt;2.7x5\P | 16.5 | 18.68 | 19.43 | 28.42 | 36.83 | 40.68 | 40.03 | 43.43 | 60.83 | 62.68 | 66.68 | 64.03 | 67.43 | 72.42 | 76.42 | 84.83 | 88.68 | 91.43 | 88.03 | 104.33 | 108.83 | 110.68 | 114.68 | 112.03 | 115.43 | 115.7 | 120.42 | 124.42 | 132.83 | 136.68 | 139.43 | 136.03 | 156.83 | 158.68 | 160.03 | 167.34 | 167.7 | 168.42 | {\Fgdt;n}\Ftxt;2.15x12 | 178.46 | {\Fgdt;n}\Ftxt;3.2x24 | 193.5 | 143.88 | 143.15 | 136.22 | 146.7 | 104.77 | 55.77 | 123.5 | 116 | 1.57 | {\Fgdt;n}\Ftxt;7 | {\Fgdt;n}\Ftxt;2.7 | {\Fgdt;n}\Ftxt;3 | 0 | 147.5 | 4 | 128.25 | 135.5 | 7.5 | 148 | 16.48 | 27.08 | 28.68 | 30 | 30.28 | 38.43 | 143.5 | 51.08 | 52.68 | 54.28 | 62.43 | 75.08 | 76.68 | 78.28 | 82.2 | 86.43 | 90.5 | 99.08 | 100.68 | 101.2 | 102.28 | 110.43 | 123.08 | 124.68 | 126.28 | 134.43 | 147.08 | 148.68 | 150.28 | 169.4 | 176.98 | {\Fgdt;n}\Ftxt;3.1x2 | 198.84 | 202.5 | 210
User.18: 148 | 4.98 | 0
User.19: {\Fgdt;n}\Ftxt;4x5\PGND_C10D4B10 | {\Fgdt;n}\Ftxt;2.7x5\P | 16.5 | 18.68 | 19.43 | 28.42 | 36.83 | 40.68 | 40.03 | 43.43 | 60.83 | 62.68 | 66.68 | 64.03 | 67.43 | 72.42 | 76.42 | 84.83 | 88.68 | 91.43 | 88.03 | 104.33 | 108.83 | 110.68 | 114.68 | 112.03 | 115.43 | 115.7 | 120.42 | 124.42 | 132.83 | 136.68 | 139.43 | 136.03 | 156.83 | 158.68 | 160.03 | 167.34 | 167.7 | 168.42 | {\Fgdt;n}\Ftxt;2.15x12 | 178.46 | {\Fgdt;n}\Ftxt;3.2x24 | 193.5 | 143.88 | 143.15 | 136.22 | 146.7 | 104.77 | 55.77 | 123.5 | 116 | 1.57 | {\Fgdt;n}\Ftxt;7 | {\Fgdt;n}\Ftxt;2.7 | {\Fgdt;n}\Ftxt;3 | 147.5 | 4 | 0 | 128.25 | 135.5 | 7.5 | 148 | 16.48 | 27.08 | 28.68 | 30 | 30.28 | 38.43 | 143.5 | 51.08 | 52.68 | 54.28 | 62.43 | 75.08 | 76.68 | 78.28 | 82.2 | 86.43 | 90.5 | 99.08 | 100.68 | 101.2 | 102.28 | 110.43 | 123.08 | 124.68 | 126.28 | 134.43 | 147.08 | 148.68 | 150.28 | 169.4 | 176.98 | {\Fgdt;n}\Ftxt;3.1x2 | 198.84 | 202.5 | 210
User.20: 148 | 4.98 | 0
User.21: {\Fgdt;n}\Ftxt;4x5\PGND_C10D4B10 | {\Fgdt;n}\Ftxt;2.7x5\P | 16.5 | 18.68 | 19.43 | 28.42 | 36.83 | 40.68 | 40.03 | 43.43 | 60.83 | 62.68 | 66.68 | 64.03 | 67.43 | 72.42 | 76.42 | 84.83 | 88.68 | 91.43 | 88.03 | 104.33 | 108.83 | 110.68 | 114.68 | 112.03 | 115.43 | 115.7 | 120.42 | 124.42 | 132.83 | 136.68 | 139.43 | 136.03 | 156.83 | 158.68 | 160.03 | 167.34 | 167.7 | 168.42 | {\Fgdt;n}\Ftxt;2.15x12 | 178.46 | {\Fgdt;n}\Ftxt;3.2x24 | 193.5 | 143.88 | 143.15 | 136.22 | 146.7 | 104.77 | 55.77 | 123.5 | 116 | 1.57 | {\Fgdt;n}\Ftxt;7 | {\Fgdt;n}\Ftxt;2.7 | {\Fgdt;n}\Ftxt;3 | 147.5 | 4 | 0 | 128.25 | 135.5 | 7.5 | 148 | 16.48 | 27.08 | 28.68 | 30 | 30.28 | 38.43 | 143.5 | 51.08 | 52.68 | 54.28 | 62.43 | 75.08 | 76.68 | 78.28 | 82.2 | 86.43 | 90.5 | 99.08 | 100.68 | 101.2 | 102.28 | 110.43 | 123.08 | 124.68 | 126.28 | 134.43 | 147.08 | 148.68 | 150.28 | 169.4 | 176.98 | {\Fgdt;n}\Ftxt;3.1x2 | 198.84 | 202.5 | 210
User.22: 148 | 4.98 | 0
User.23: {\Fgdt;n}\Ftxt;4x5\PGND_C10D4B10 | {\Fgdt;n}\Ftxt;2.7x5\P | 16.5 | 18.68 | 19.43 | 28.42 | 36.83 | 40.68 | 40.03 | 43.43 | 60.83 | 62.68 | 66.68 | 64.03 | 67.43 | 72.42 | 76.42 | 84.83 | 88.68 | 91.43 | 88.03 | 104.33 | 108.83 | 110.68 | 114.68 | 112.03 | 115.43 | 115.7 | 120.42 | 124.42 | 132.83 | 136.68 | 139.43 | 136.03 | 156.83 | 158.68 | 160.03 | 167.34 | 167.7 | 168.42 | {\Fgdt;n}\Ftxt;2.15x12 | 178.46 | {\Fgdt;n}\Ftxt;3.2x24 | 193.5 | 143.88 | 143.15 | 136.22 | 146.7 | 104.77 | 55.77 | 123.5 | 116 | 1.57 | {\Fgdt;n}\Ftxt;7 | {\Fgdt;n}\Ftxt;2.7 | {\Fgdt;n}\Ftxt;3 | 147.5 | 4 | 0 | 128.25 | 135.5 | 7.5 | 148 | 16.48 | 27.08 | 28.68 | 30 | 30.28 | 38.43 | 143.5 | 51.08 | 52.68 | 54.28 | 62.43 | 75.08 | 76.68 | 78.28 | 82.2 | 86.43 | 90.5 | 99.08 | 100.68 | 101.2 | 102.28 | 110.43 | 123.08 | 124.68 | 126.28 | 134.43 | 147.08 | 148.68 | 150.28 | 169.4 | 176.98 | {\Fgdt;n}\Ftxt;3.1x2 | 198.84 | 202.5 | 210
User.24: 148 | 4.98 | 0
User.25: TOP | 1
User.26: BOTTOM | 10
User.27: SILK-TOP
User.28: SILK-BOT
User.29: MASK-TOP
User.30: MASK-BOT
User.31: FAB
User.32: PAST-TOP
User.33: PAST-BOT
User.34: GND | 2
User.35: VCC | 5
User.36: IN1 | 3
User.37: IN2 | 8
User.38: VCC1 | 6
User.39: GND1 | 4
User.40: PANEL
User.42: GND2 | 7
User.43: GND3 | 9
